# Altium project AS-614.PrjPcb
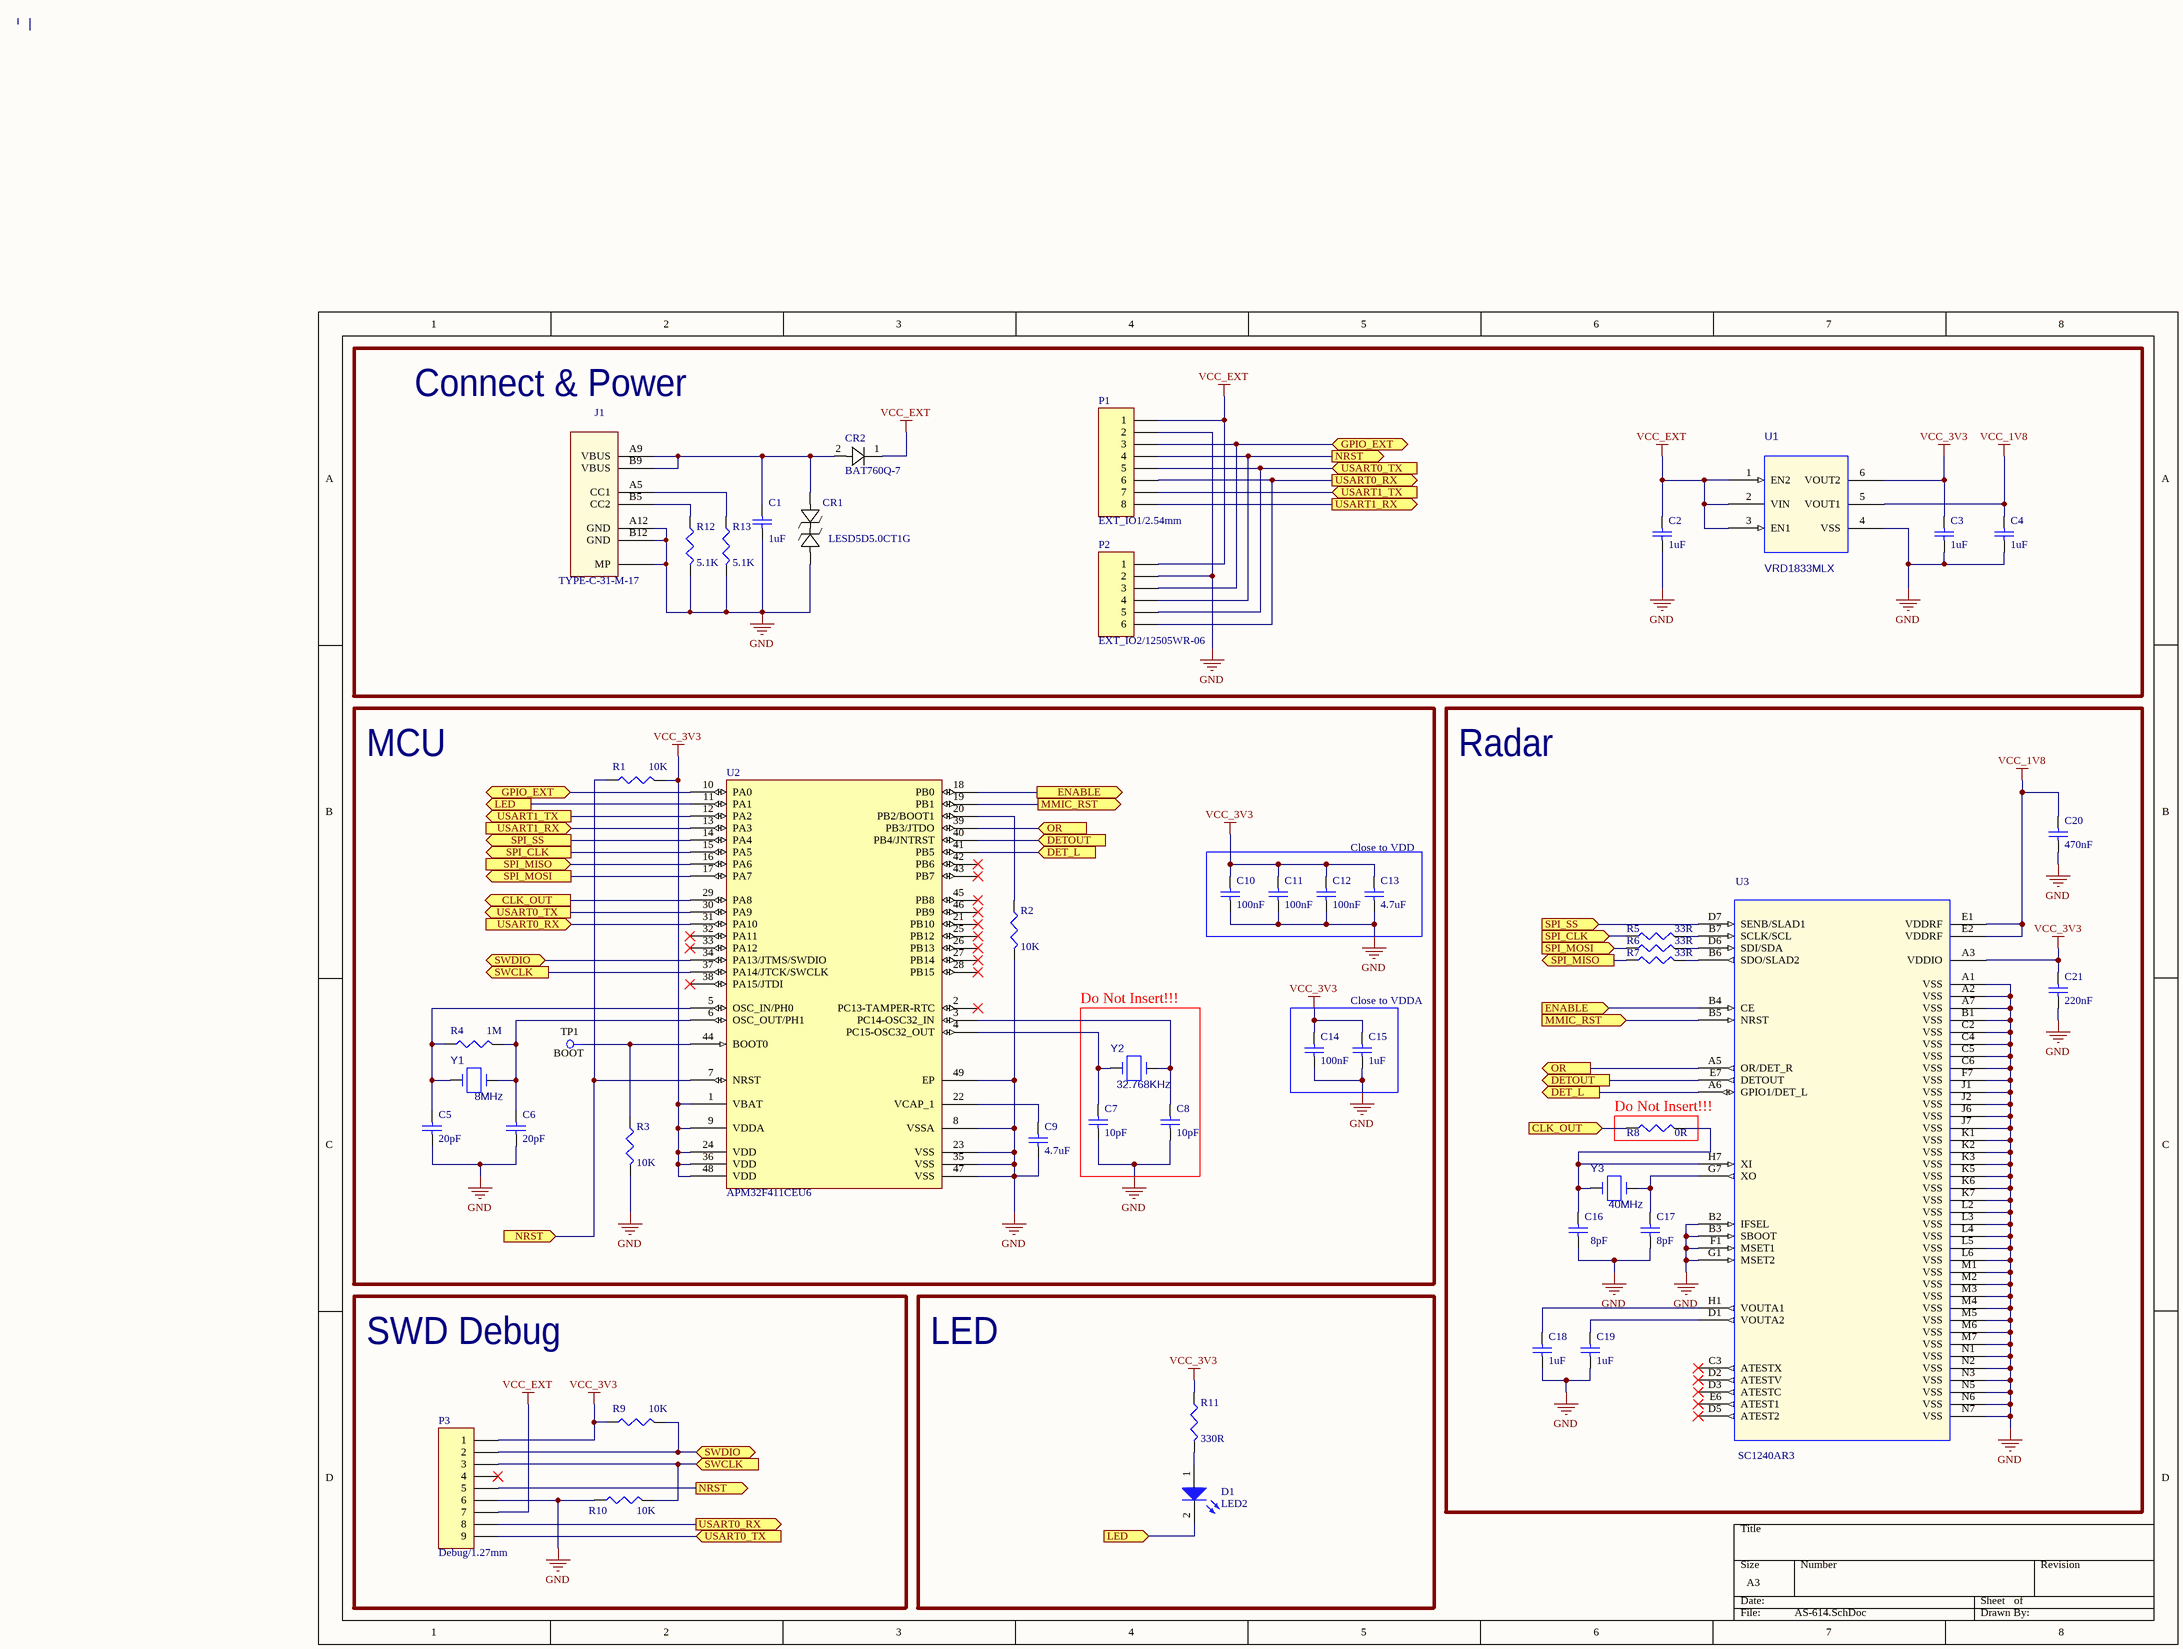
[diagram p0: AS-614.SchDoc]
1 sheet, 48 parts. Net scope: flat (ports and power ports of the same name join across sheets).
Board file: AS-614.PcbDoc

## Sheet AS-614.SchDoc
size A3; SheetNumber: 1; SheetTotal: 1; SPICEModelCacheIQYXKOUW: <root> / <DocumentId>IQYXKOUW</DocumentId> / <CacheFrame Number="0"> / <Model Name="led2" Kind="MDL"> / <Text>*Typ RED,GREEN,YELLOW,AMBER GaAs LED: Vf=2.1V Vr=4V If=40mA trr=3uS / *LED Pinout: 1=A, 2=K / .MODEL LED2 D (IS=93.1P RS=42M N=4.61 BV=4 IBV=10U / + CJO=2.97P VJ=.75 M=.333 TT=4.32U)</Text> / </Model> / <Model Name="cap" Kind="MDL"> / <Text>*Default semiconductor capacitor / .MODEL CAP C()</Text> / </Model> / </CacheFrame> / </root>

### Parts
C1  value 1uF  [CAP 0402/1005]  (hidden comment: Cap Semi)
C2  value 1uF  [CAP 0402/1005]  (hidden comment: Cap Semi)
C3  value 1uF  [CAP 0402/1005]  (hidden comment: Cap Semi)
C4  value 1uF  [CAP 0402/1005]  (hidden comment: Cap Semi)
C5  value 20pF  [CAP 0402/1005]  (hidden comment: Cap Semi)
C6  value 20pF  [CAP 0402/1005]  (hidden comment: Cap Semi)
C7  value 10pF  [CAP 0402/1005]  (hidden comment: Cap Semi)
C8  value 10pF  [CAP 0402/1005]  (hidden comment: Cap Semi)
C9  value 4.7uF  [CAP 0402/1005]  (hidden comment: Cap Semi)
C10  value 100nF  [CAP 0402/1005]  (hidden comment: Cap Semi)
C11  value 100nF  [CAP 0402/1005]  (hidden comment: Cap Semi)
C12  value 100nF  [CAP 0402/1005]  (hidden comment: Cap Semi)
C13  value 4.7uF  [CAP 0402/1005]  (hidden comment: Cap Semi)
C14  value 100nF  [CAP 0402/1005]  (hidden comment: Cap Semi)
C15  value 1uF  [CAP 0402/1005]  (hidden comment: Cap Semi)
C16  value 8pF  [CAP 0402/1005]  (hidden comment: Cap Semi)
C17  value 8pF  [CAP 0402/1005]  (hidden comment: Cap Semi)
C18  value 1uF  [CAP 0402/1005]  (hidden comment: Cap Semi)
C19  value 1uF  [CAP 0402/1005]  (hidden comment: Cap Semi)
C20  value 470nF  [CAP 0402/1005]  (hidden comment: Cap Semi)
C21  value 220nF  [CAP 0402/1005]  (hidden comment: Cap Semi)
CR1  LESD5D5.0CT1G  [SOD523]
CR2  BAT760Q-7  [SOD-323 - 21]
D1  LED2  [LED 0603/1608 RED]
J1  TYPE-C-31-M-17  [CON/USB-C/6P-1]
P1  EXT_IO1/2.54mm  [Pin Header 1x8 TH Pitch 2.54mm]
P2  EXT_IO2/12505WR-06  [12505WR-06/53261-0671]
P3  Debug/1.27mm  [PIN HEADER 1X9 TH 1.27mm]
R1  value 10K  [RES 0402/1005]  (hidden comment: Res3)
R2  value 10K  [RES 0402/1005]  (hidden comment: Res3)
R3  value 10K  [RES 0402/1005]  (hidden comment: Res3)
R4  value 1M  [RES 0402/1005]  (hidden comment: Res3)
R5  value 33R  [RES 0402/1005]  (hidden comment: Res3)
R6  value 33R  [RES 0402/1005]  (hidden comment: Res3)
R7  value 33R  [RES 0402/1005]  (hidden comment: Res3)
R8  value 0R  [RES 0402/1005]  (hidden comment: Res3)
R9  value 10K  [RES 0402/1005]  (hidden comment: Res3)
R10  value 10K  [RES 0402/1005]  (hidden comment: Res3)
R11  value 330R  [RES 0402/1005]  (hidden comment: Res3)
R12  value 5.1K  [RES 0402/1005]  (hidden comment: Res3)
R13  value 5.1K  [RES 0402/1005]  (hidden comment: Res3)
TP1  BOOT  [TP/0.6 / SMD]  (no BOM)
U1  VRD1833MLX  [LLP-6 / L2.0-W1.8-P0.50-BL-EP]
U2  APM32F411CEU6  [VQFN-48/ QFN50P700X700X100-49N]
U3  SC1240AR3  [BGA62 7X4]
Y1  value 8MHz  [XTAL_3225]  (hidden comment: CRYSTAL13)
Y2  value 32.768KHz  [XTAL/3215]  (hidden comment: CRYSTAL13)
Y3  value 40MHz  [XTAL_3225]  (hidden comment: CRYSTAL13)

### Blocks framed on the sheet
Connect & Power: C1-C4 CR1 CR2 J1 P1 P2 R12 R13 U1
MCU: C5 C6 C9 R1-R4 TP1 U2 Y1
Radar: C16-C21 R5-R8 U3 Y3
Close to VDD: C10-C13
Do Not Insert!!!: C7 C8 Y2
Close to VDDA: C14 C15
SWD Debug: P3 R9 R10
LED: D1 R11

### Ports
CLK_OUT (in), CLK_OUT (out), DET_L (in), DET_L (out), DETOUT (in), DETOUT (out), ENABLE (in), ENABLE (out), GPIO_EXT (bidir), LED (in), LED (out), MMIC_RST (in), MMIC_RST (out), NRST (in), NRST (out), OR (in), OR (out), SPI_CLK (in), SPI_CLK (out), SPI_MISO (in), SPI_MISO (out), SPI_MOSI (in), SPI_MOSI (out), SPI_SS (in), SPI_SS (out), SWCLK (in), SWCLK (out), SWDIO (bidir), USART0_RX (in), USART0_RX (out), USART0_TX (in), USART0_TX (out), USART1_RX (in), USART1_RX (out), USART1_TX (in), USART1_TX (out)

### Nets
GND: C1.1 C2.1 C3.1 C4.1 C5.1 C6.1 C7.1 C8.1 C9.1 C10.1 C11.1 C12.1 C13.1 C14.1 C15.1 C16.1 C17.1 C18.1 C19.1 C20.1 C21.1 CR1.2 J1.A12(GND) J1.B12(GND) J1.MP P1.2 P2.2 P3.6 R2.2 R3.2 R10.1 R12.2 R13.2 U1.4(VSS) U2.8(VSSA) U2.23(VSS) U2.35(VSS) U2.47(VSS) U2.49(EP) U3.A1(VSS) U3.A2(VSS) U3.A7(VSS) U3.B1(VSS) U3.B2(IFSEL) U3.B3(SBOOT) U3.C2(VSS) U3.C4(VSS) U3.C5(VSS) U3.C6(VSS) U3.F1(MSET1) U3.F7(VSS) U3.G1(MSET2) U3.J1(VSS) U3.J2(VSS) U3.J6(VSS) U3.J7(VSS) U3.K1(VSS) U3.K2(VSS) U3.K3(VSS) U3.K5(VSS) U3.K6(VSS) U3.K7(VSS) U3.L2(VSS) U3.L3(VSS) U3.L4(VSS) U3.L5(VSS) U3.L6(VSS) U3.M1(VSS) U3.M2(VSS) U3.M3(VSS) U3.M4(VSS) U3.M5(VSS) U3.M6(VSS) U3.M7(VSS) U3.N1(VSS) U3.N2(VSS) U3.N3(VSS) U3.N5(VSS) U3.N6(VSS) U3.N7(VSS)
VCC_1V8: C4.2 C20.2 U1.5(VOUT1) U3.E1(VDDRF) U3.E2(VDDRF)
VCC_3V3: C3.2 C10.2 C11.2 C12.2 C13.2 C14.2 C15.2 C21.2 P3.1 R1.2 R9.1 R11.1 U1.6(VOUT2) U2.1(VBAT) U2.9(VDDA) U2.24(VDD) U2.36(VDD) U2.48(VDD) U3.A3(VDDIO)
VCC_EXT: C2.2 CR2.1 P1.1 P2.1 P3.7 U1.1(EN2) U1.2(VIN) U1.3(EN1)
NetC1_2: C1.2 CR1.1 CR2.2 J1.A9(VBUS) J1.B9(VBUS)
NetC5_2: C5.2 R4.1 U2.5(OSC_IN/PH0) Y1.1
NetC6_2: C6.2 R4.2 U2.6(OSC_OUT/PH1) Y1.3
NetC7_2: C7.2 U2.4(PC15-OSC32_OUT) Y2.1
NetC8_2: C8.2 U2.3(PC14-OSC32_IN) Y2.2
NetC9_2: C9.2 U2.22(VCAP_1)
NetC16_2: C16.2 R8.2 U3.H7(XI) Y3.1
NetC17_2: C17.2 U3.G7(XO) Y3.3
NetC18_2: C18.2 U3.H1(VOUTA1)
NetC19_2: C19.2 U3.D1(VOUTA2)
NetD1_1: D1.1(A) R11.2
NetD1_2: D1.2(K) U2.11(PA1) ; port LED
NetJ1_A5: J1.A5(CC1) R13.1
NetJ1_B5: J1.B5(CC2) R12.1
NetP1_3: P1.3 P2.3 U2.10(PA0) ; port GPIO_EXT
NetP1_4: P1.4 P2.4 P3.5 R1.1 U2.7(NRST) ; port NRST
NetP1_5: P1.5 P2.5 P3.9 U2.30(PA9) ; port USART0_TX
NetP1_6: P1.6 P2.6 P3.8 U2.31(PA10) ; port USART0_RX
NetP1_7: P1.7 U2.12(PA2) ; port USART1_TX
NetP1_8: P1.8 U2.13(PA3) ; port USART1_RX
NetP3_2: P3.2 R9.2 U2.34(PA13/JTMS/SWDIO) ; port SWDIO
NetP3_3: P3.3 R10.2 U2.37(PA14/JTCK/SWCLK) ; port SWCLK
NetR2_1: R2.1 U2.20(PB2/BOOT1)
NetR3_1: R3.1 TP1.1 U2.44(BOOT0)
NetR5_1: R5.1 U2.15(PA5) ; port SPI_CLK
NetR5_2: R5.2 U3.B7(SCLK/SCL)
NetR6_1: R6.1 U2.17(PA7) ; port SPI_MOSI
NetR6_2: R6.2 U3.D6(SDI/SDA)
NetR7_1: R7.1 U2.16(PA6) ; port SPI_MISO
NetR7_2: R7.2 U3.B6(SDO/SLAD2)
NetR8_1: R8.1 U2.29(PA8) ; port CLK_OUT
NetU2_14: U2.14(PA4) U3.D7(SENB/SLAD1) ; port SPI_SS
NetU2_18: U2.18(PB0) U3.B4(CE) ; port ENABLE
NetU2_19: U2.19(PB1) U3.B5(NRST) ; port MMIC_RST
NetU2_39: U2.39(PB3/JTDO) U3.A5(OR/DET_R) ; port OR
NetU2_40: U2.40(PB4/JNTRST) U3.E7(DETOUT) ; port DETOUT
NetU2_41: U2.41(PB5) U3.A6(GPIO1/DET_L) ; port DET_L

Not connected (* = marked no-connect by the designer): P3 4*; U2 2(PC13-TAMPER-RTC)* 21(PB10)* 25(PB12)* 26(PB13)* 27(PB14)* 28(PB15)* 32(PA11)* 33(PA12)* 38(PA15/JTDI)* 42(PB6)* 43(PB7)* 45(PB8)* 46(PB9)*; U3 C3(ATESTX)* D2(ATESTV)* D3(ATESTC)* D5(ATEST2)* E6(ATEST1)*

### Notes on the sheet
- (near U3) Do Not Insert!!!

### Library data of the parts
C1-C21 = Cap Semi: Capacitor (Semiconductor SIM Model)
CR1 = LESD5D5.0CT1G: No Description Available; Mfr_Name: UMW(Youtai Semiconductor Co., Ltd.); Type: Current Regulation - Diodes, Transistors
CR2 = BAT760Q-7: No Description Available; Mfr_Name: Diodes Inc
D1 = LED2: Typical RED, GREEN, YELLOW, AMBER GaAs LED
J1 = CON/USB-C/6P: 6P C-type Connector; PCB DECAL: 20160406_T
P1 = Header 8: Header, 8-Pin
P2 = Header 6: Header, 6-Pin
P3 = Header 9: Header, 9-Pin
R1-R13 = Res3: Resistor
TP1 = TP: Test Point; Manufacturer: Keystone; CompType: Test Point Loop; ContactFinish: Silver
U1 = VRD1833MLX: Part Reference: U1
Y1-Y3 = CRYSTAL13: Part Reference: Y2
